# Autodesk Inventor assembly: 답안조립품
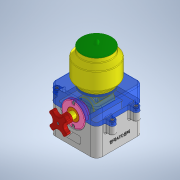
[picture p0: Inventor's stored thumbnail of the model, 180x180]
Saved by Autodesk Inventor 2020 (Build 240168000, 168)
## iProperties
Created: 2022-03
Part Number: 답안조립품
Document SubType Name: Assembly
Designer: Administrator
Author: Administrator
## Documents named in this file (11)
- C:\Users\Administrator\Desktop\720306V1015\답안조립품.iam
- C:\Users\Administrator\Desktop\720306V1015\본체.ipt
- C:\Users\Administrator\Desktop\720306V1015\본체커버.ipt
- C:\Users\Administrator\Desktop\720306V1015\용기.ipt
- C:\Users\Administrator\Desktop\720306V1015\용기캡.ipt
- C:\Users\Administrator\Desktop\720306V1015\앞커버.ipt
- C:\Users\Administrator\Desktop\720306V1015\핸들축.ipt
- C:\Users\Administrator\Desktop\720306V1015\볼트 M4x12.ipt
- C:\Users\Administrator\Desktop\720306V1015\핸들.ipt
- C:\Users\Administrator\Desktop\720306V1015\볼트 M3x12.ipt
- C:\Users\Administrator\Desktop\720306V1015\베어링 부시.ipt
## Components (2 placed, 2 different names)
1. 핸들축:1
2. 핸들:1
